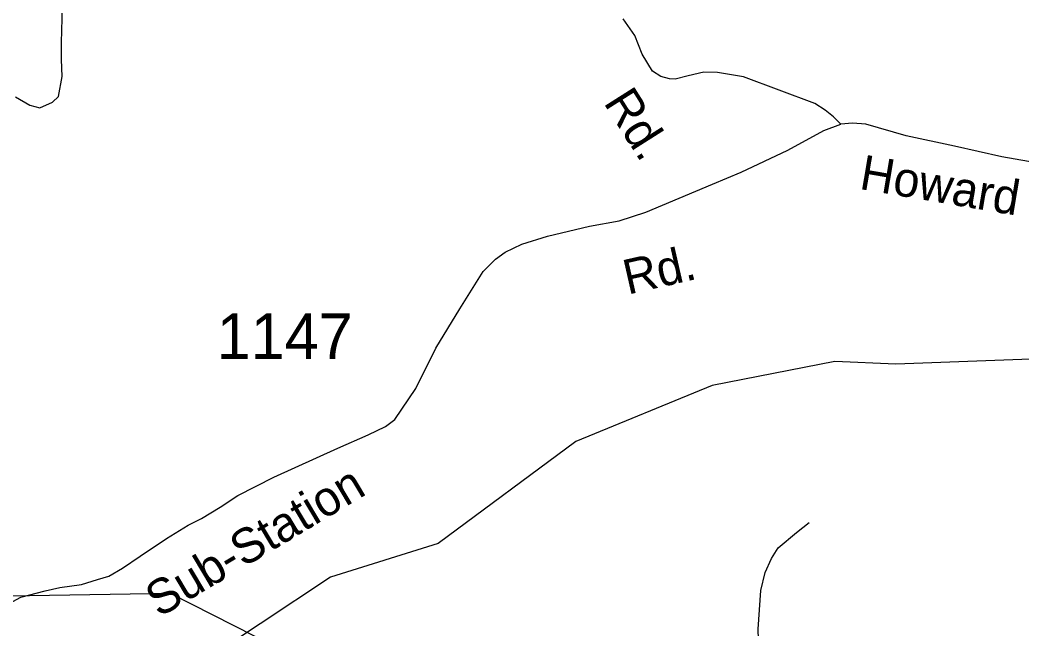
# Model space of a CAD drawing. Extents: x 990631 to 1056237, y 535999 to 585651.
# Drawn here: x 1001128 to 1003866, y 560648 to 562312 of the extents above; entities that cross this region are included whole.
import ezdxf

# ---------------------------------------------------------------- set-up
doc = ezdxf.new("R2010")
doc.units = 0
for name, color, linetype in [('Exist Boundary Political City Limit New', 7, 'Continuous'), ('Exist Hydrographic Creek Single Shore', 7, 'Continuous'), ('Exist Road Non-System Type 51', 7, 'Continuous'), ('Exist Road Secondary Type 41 Attributed', 7, 'Continuous'), ('Exist Road Secondary Type 51 Attributed', 7, 'Continuous'), ('Exist Road Secondary Type 51 Label', 7, 'Continuous'), ('Exist Road Secondary Type 51 Number Label', 7, 'Continuous')]:
    doc.layers.add(name, color=color, linetype=linetype)

msp = doc.modelspace()

# ---------------------------------------------------------------- linework, layer by layer
at = {"layer": 'Exist Boundary Political City Limit New'}
msp.add_lwpolyline([(1002001.6, 560510.7), (1001538.9, 560745.4), (1000657, 560730.8)], dxfattribs=at)
at = {"layer": 'Exist Hydrographic Creek Single Shore'}
msp.add_lwpolyline([(1006853, 560510.9), (1006857.7, 560651.9), (1006903.1, 560759.4), (1006899.4, 560900.5), (1006777.9, 561004.8), (1006646.2, 561059.9), (1006262.6, 561057.8), (1005815.1, 561139), (1005569.1, 561262.2), (1005391.1, 561426.6), (1005030.9, 561381.3), (1004730.5, 561374.3), (1004479.2, 561339.9), (1003988.9, 561389.2), (1003521.4, 561372.3), (1003354.7, 561379), (1003019.1, 561313.6), (1002647, 561160.3), (1002270.9, 560882.3), (1001975.9, 560789.9), (1001592.3, 560535)], dxfattribs=at)
msp.add_lwpolyline([(1006853, 560510.9), (1006857.7, 560651.9), (1006903.1, 560759.4), (1006899.4, 560900.5), (1006777.9, 561004.8), (1006646.2, 561059.9), (1006262.6, 561057.8), (1005815.1, 561139), (1005569.1, 561262.2), (1005391.1, 561426.6), (1005030.9, 561381.3), (1004730.5, 561374.3), (1004479.2, 561339.9), (1003988.9, 561389.2), (1003521.4, 561372.3), (1003354.7, 561379), (1003019.1, 561313.6), (1002647, 561160.3), (1002270.9, 560882.3), (1001975.9, 560789.9), (1001592.3, 560535)], dxfattribs=at)
at = {"layer": 'Exist Road Non-System Type 51'}
msp.add_lwpolyline([(1003116.4, 560402.3), (1003131.4, 560433.8), (1003138.4, 560459.7), (1003145.4, 560493.4), (1003147.6, 560561.3), (1003144.6, 560647.6), (1003152.1, 560753.3), (1003163.7, 560803.1), (1003181.1, 560840.6), (1003200.1, 560869.8), (1003249.5, 560912.2), (1003284.3, 560939.1)], dxfattribs=at)
at = {"layer": 'Exist Road Secondary Type 41 Attributed'}
msp.add_lwpolyline([(1003370.9, 562028), (1003351.3, 562047.6), (1003328.1, 562065.5), (1003299.6, 562083.9), (1003105, 562156.7), (1003033.9, 562169), (1002996.2, 562170), (1002954.1, 562160.1), (1002918.5, 562150.2), (1002902.7, 562151.2), (1002878.9, 562157.6), (1002856.1, 562172.5), (1002827.9, 562219.1), (1002807.6, 562270.2), (1002776.3, 562315.3)], dxfattribs=at)
at = {"layer": 'Exist Road Secondary Type 51 Attributed'}
for points in [[(1001115.3, 562101.9), (1001154.5, 562079.6), (1001182.2, 562072.7), (1001216.8, 562087.5), (1001233, 562102.8), (1001242.6, 562157.6), (1001241.6, 562204.5), (1001240.9, 562251.1), (1001244.6, 562383.2)], [(1001074.7, 560705.4), (1001130.1, 560734.9), (1001196.5, 560752.4), (1001237.1, 560761.4), (1001295.6, 560770.2), (1001339.2, 560783.1), (1001370.8, 560793), (1001407.5, 560814.8), (1001456, 560847.5), (1001527.7, 560895.7), (1001587, 560931.8), (1001623.6, 560950.4), (1001674.7, 560980.8), (1001723.4, 561012.9), (1001821.5, 561063.5), (1001996.7, 561142.2), (1002078.9, 561178.9), (1002126.5, 561201.6), (1002152.2, 561220.5), (1002209.7, 561305.6), (1002264.1, 561415.6), (1002329.5, 561523.1), (1002393.9, 561625.1), (1002427.5, 561658.8), (1002453.3, 561677.6), (1002498.8, 561699.4), (1002569.2, 561721.7), (1002684, 561749.4), (1002765.2, 561763.3), (1002838.5, 561787.1), (1003019.8, 561863.8), (1003099, 561896.5), (1003225.8, 561956.9), (1003324.8, 562010.4), (1003370.9, 562028)], [(1005128.4, 561577.3), (1004750.7, 561706.3), (1004666.6, 561737.6), (1004588.3, 561767), (1004537.4, 561786.6), (1004465, 561814), (1004396.5, 561839.5), (1004339.8, 561849.3), (1004245.9, 561859), (1004128.4, 561882.5), (1003811.2, 561938.6), (1003681.6, 561967.7), (1003549.2, 561996.1), (1003439.7, 562027.4), (1003402.4, 562030.4), (1003370.9, 562028)]]:
    msp.add_lwpolyline(points, dxfattribs=at)

# ---------------------------------------------------------------- texts
at = {"layer": 'Exist Road Secondary Type 51 Label'}
for s, rotation, p in [('Rd.', 302.3764, (1002720.8, 562086.8)), ('Rd.', 302.3764, (1002720.8, 562086.8)), ('Howard', 350.3847, (1003418.9, 561851)), ('Howard', 350.3847, (1003418.9, 561851)), ('Rd.', 12.8451, (1002788.5, 561561.5)), ('Rd.', 12.8451, (1002788.5, 561561.5)), ('Sub-Station', 30.7689, (1001507.9, 560678.2)), ('Sub-Station', 30.7689, (1001507.9, 560678.2))]:
    msp.add_text(s, height=95, rotation=rotation, dxfattribs=at).set_placement(p)
at = {"layer": 'Exist Road Secondary Type 51 Number Label'}
msp.add_text('1147', height=125, dxfattribs=at).set_placement((1001665.1, 561385.8))

doc.saveas('drawing.dxf')
